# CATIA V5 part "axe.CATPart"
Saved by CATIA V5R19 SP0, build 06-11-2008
Part number: axe
Bounding box of the stored display mesh (mm): x 0 to 40.1, y -11 to 11, z -11 to 11
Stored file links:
  G:\project guitar elect\axe.CATPart
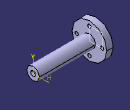
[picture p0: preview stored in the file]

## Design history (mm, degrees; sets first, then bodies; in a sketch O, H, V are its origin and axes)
Body1 (main body)
  Sketch1 on yz-plane, origin (0, 0, 0), H (0, 1, 0), V (0, 0, 1)
    circle A1 centre (0, 0) radius 4
    radius A1 = 4
  Pad1: profile Sketch1, direction (1, 0, 0), length 40.1
  Plane1: type Offset, Offset 0.7, RefPlane yz-plane
  Sketch2 on Plane1, origin (0.7, 0, 0), H (0, 1, 0), V (0, 0, 1)
    circle A1 centre (0, 0) radius 11
    radius A1 = 11
  Pad2: profile Sketch2, direction (1, 0, 0), length 4
  Sketch3 on start face of Pad2, origin (0.7, 0, 0), H (0, -1, 0), V (0, 0, 1)
    circle A1 centre (0, 8) radius 1.1
    point P1 (0, 8)
    axis line L1 (-9.1, 0) -> (6.9, 0)
    point P2 (-9.1, 0)
    point P3 (6.9, 0)
    circle A2 centre (0, -8) radius 1.1
    circle A3 centre (8, 0) radius 1.1
    point P5 (8, 0)
    circle A4 centre (-8, 0) radius 1.1
    point P6 (-8, 0)
    distance P1 A1 = 1.1
    radius A3 = 1.1
    radius A4 = 1.1
    coincidence: P1 V, P5 H, A3 P3, P6 L1, A4 P2
    horizontal: L1 H
    symmetry: A1 A2 L1
  Pocket1: profile Sketch3, direction (1, 0, 0), length 4
  Sketch4 on start face of Pad1, origin (0, 0, 0), H (0, -1, 0), V (0, 0, 1)
    circle A1 centre (0, 0) radius 2.8
    radius A1 = 2.8
  Pocket2: profile Sketch4, direction (1, 0, 0), length 0.7
  Sketch5 on end face of Pocket2, origin (0.7, 0, 0), H (0, -1, 0), V (0, 0, 1)
    circle A1 centre (0, 0) radius 1.4
    radius A1 = 1.4
  Pocket3: profile Sketch5, direction (1, 0, 0), length 5
  Sketch6 on end face of Pad1, origin (40.1, 0, 0), H (0, 1, 0), V (0, 0, 1)
    reference projected circle E1 centre (0, 0) radius 4 from edge [face of Pad1 from Sketch1.A1 | end face of Pad1]
    radius E1 = 4 (reference)
  Sketch7 on end face of Pad1, origin (40.1, 0, 0), H (0, 1, 0), V (0, 0, 1)
    circle A1 centre (0, 0) radius 1.6
    radius A1 = 1.6
  Pocket4: profile Sketch7, direction (-1, 0, 0), length 1.5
